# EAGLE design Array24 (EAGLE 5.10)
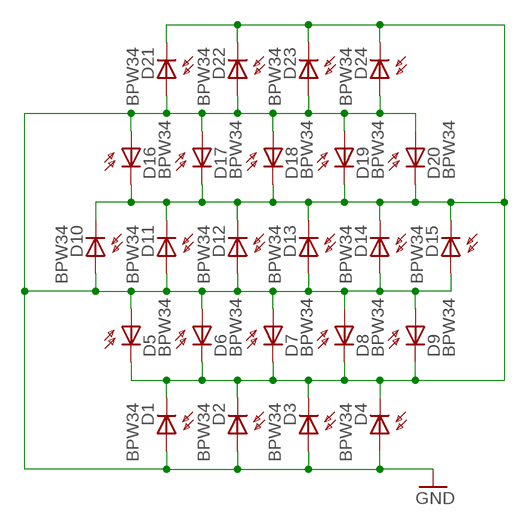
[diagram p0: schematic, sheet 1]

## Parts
D1  BPW34  [BPW34]
D2  BPW34  [BPW34]
D3  BPW34  [BPW34]
D4  BPW34  [BPW34]
D5  BPW34  [BPW34]
D6  BPW34  [BPW34]
D7  BPW34  [BPW34]
D8  BPW34  [BPW34]
D9  BPW34  [BPW34]
D10  BPW34  [BPW34]
D11  BPW34  [BPW34]
D12  BPW34  [BPW34]
D13  BPW34  [BPW34]
D14  BPW34  [BPW34]
D15  BPW34  [BPW34]
D16  BPW34  [BPW34]
D17  BPW34  [BPW34]
D18  BPW34  [BPW34]
D19  BPW34  [BPW34]
D20  BPW34  [BPW34]
D21  BPW34  [BPW34]
D22  BPW34  [BPW34]
D23  BPW34  [BPW34]
D24  BPW34  [BPW34]

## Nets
GND: D1.A D2.A D3.A D4.A D5.A D6.A D7.A D8.A D9.A D10.A D11.A D12.A D13.A D14.A D15.A D16.A D17.A D18.A D19.A D20.A D21.A D22.A D23.A D24.A
N$4: D1.K(C) D2.K(C) D3.K(C) D4.K(C) D5.K(C) D6.K(C) D7.K(C) D8.K(C) D9.K(C) D10.K(C) D11.K(C) D12.K(C) D13.K(C) D14.K(C) D15.K(C) D16.K(C) D17.K(C) D18.K(C) D19.K(C) D20.K(C) D21.K(C) D22.K(C) D23.K(C) D24.K(C)

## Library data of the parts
D1-D24 = 00-LIVIO:BPW34: PHOTO DIODE

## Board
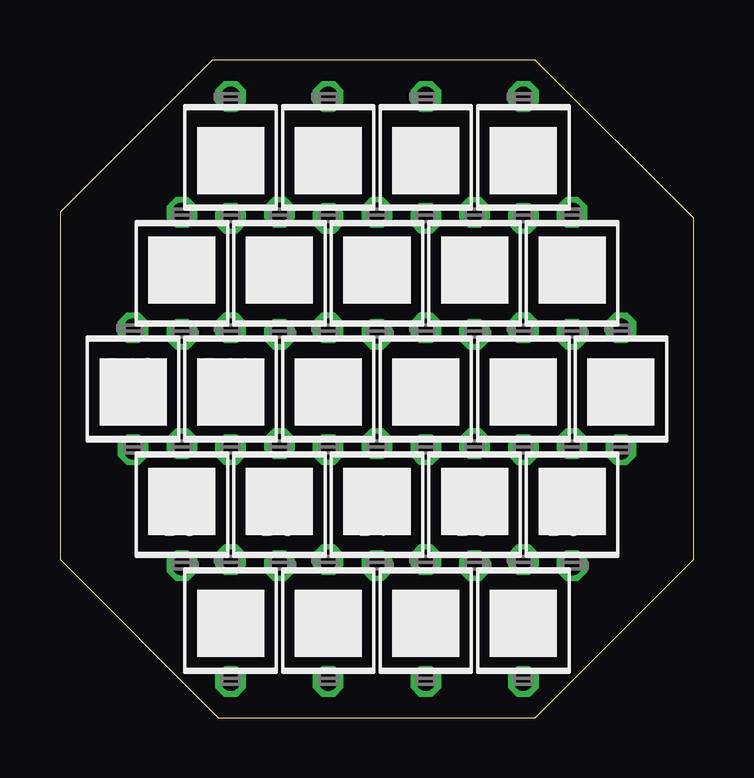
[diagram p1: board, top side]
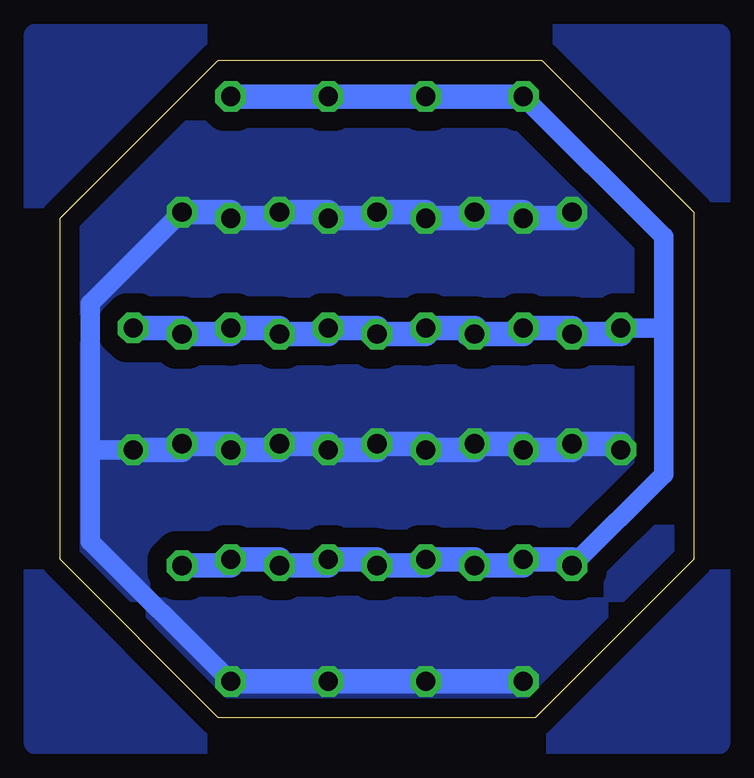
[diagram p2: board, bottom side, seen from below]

Size 26.42 x 27.43 mm. Coordinates in mm from the lower left corner, seen from the top.
Outline: 0,6.6 6.6,0 19.81,0 26.42,6.6 26.42,20.83 19.81,27.43 6.35,27.43 0,21.08 0,6.6
Copper layers (1*16): Top 0.035mm / dielectric 1.5mm / Bottom 0.035mm
Design rules "FastGcode-DesignRules": minimum track width 10mil, minimum drill 0.6mm, track to track 8mil, track to pad 8mil, pad to pad 8mil, via to via 8mil, smd to smd 8mil, copper to edge 31mil, drill to drill 8mil, minimum pad ring 5mil, minimum via ring 8mil, stop-mask expansion 4mil, vias tented up to drill 0mil, thermal gap 41mil

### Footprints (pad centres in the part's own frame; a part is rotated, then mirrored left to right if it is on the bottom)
BPW34 = drill 0.8 pad 1.27 octagon: A 0,2.54; K 0,-2.54

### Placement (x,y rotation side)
D1  7.11,4.06 180 top
D2  11.18,4.06 180 top
D3  15.24,4.06 180 top
D4  19.3,4.06 180 top
D5  5.08,8.89 0 top
D6  9.14,8.89 0 top
D7  13.21,8.89 0 top
D8  17.27,8.89 0 top
D9  21.34,8.89 0 top
D10  3.05,13.72 180 top
D11  7.11,13.72 180 top
D12  11.18,13.72 180 top
D13  15.24,13.72 180 top
D14  19.3,13.72 180 top
D15  23.37,13.72 180 top
D16  5.08,18.54 0 top
D17  9.14,18.54 0 top
D18  13.21,18.54 0 top
D19  17.27,18.54 0 top
D20  21.34,18.54 0 top
D21  7.11,23.37 180 top
D22  11.18,23.37 180 top
D23  15.24,23.37 180 top
D24  19.3,23.37 180 top

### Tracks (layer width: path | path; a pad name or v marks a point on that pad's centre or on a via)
GND
  Bottom 0.813: 25.15,11.18 25.15,17.27 D20.A | 25.15,11.18 D15.A | 25.15,11.18 25.15,7.37 D4.A
  Bottom 1.016: D1.A D2.A D3.A D4.A | D10.A 3.05,11.43 D5.A 5.08,11.18 D11.A 7.11,11.43 D6.A 9.14,11.18 D12.A 11.18,11.43 D7.A 13.21,11.18 D13.A 15.24,11.43 D8.A 17.27,11.18 D14.A 19.3,11.43 D9.A 21.34,11.18 D15.A | D16.A 5.08,20.83 D21.A 7.11,21.08 D17.A 9.14,20.83 D22.A 11.18,21.08 D18.A 13.21,20.83 D23.A 15.24,21.08 D19.A 17.27,20.83 D24.A 19.3,21.08 D20.A
  pour Bottom (isolate 0.8, no thermals): -1,-1 27.42,-1 27.42,28.43 -1,28.43
N$4
  Bottom 0.813: 1.27,16.26 1.27,20.07 D21.K | 1.27,16.26 D10.K | 1.27,16.26 1.27,10.16 D5.K
  Bottom 1.016: D5.K 5.08,6.6 D1.K 7.11,6.35 D6.K 9.14,6.6 D2.K 11.18,6.35 D7.K 13.21,6.6 D3.K 15.24,6.35 D8.K 17.27,6.6 D4.K 19.3,6.35 D9.K | D10.K 3.05,16 D16.K 5.08,16.26 D11.K 7.11,16 D17.K | D17.K 9.4,16 | D17.K 9.14,16.26 D12.K 11.18,16 D18.K 13.21,16.26 D13.K 15.24,16 D19.K 17.27,16.26 D14.K 19.3,16 D20.K 21.34,16.26 D15.K | D21.K D22.K D23.K D24.K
